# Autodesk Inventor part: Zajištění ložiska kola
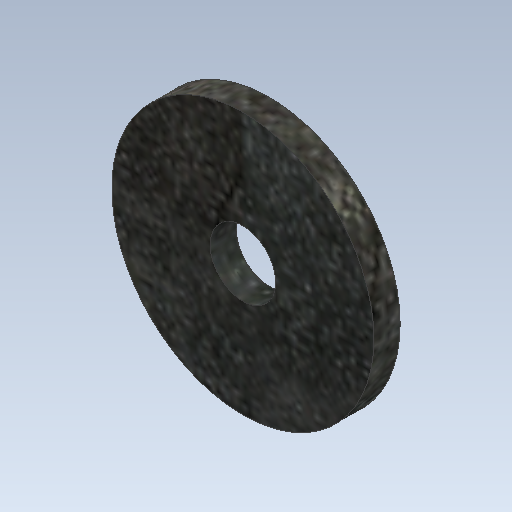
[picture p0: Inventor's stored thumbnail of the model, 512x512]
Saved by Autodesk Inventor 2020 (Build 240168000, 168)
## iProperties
Created: 2025-03
Part Number: Zajištění ložiska kola
Material: Ocel
Document SubType Name: Modeling
Designer: doma
Density: 7.85 g/cm^3
Appearance: Plech
Mass: 36.9923 g
Surface Area: 29.8451 cm^2
Volume: 4.71239 cm^3
Author: doma
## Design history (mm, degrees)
sketch "Náčrt1"
  geometry: C1 r 5 at (0, 0); C2 r 20 at (0, 0); 1 further point
  constraints: 2 centre point, 2 coincident
  dimensions: "d0" = 10 diameter of C1; "d1" = 40 diameter of C2
extrude "Vysunutí1" new body sketch "Náčrt1" distance "d3" = 4; taper "d4" = 0 deg
node "Těleso1"
